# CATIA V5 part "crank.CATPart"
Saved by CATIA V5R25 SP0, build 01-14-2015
Part number: crank
Bounding box of the stored display mesh (mm): x 0 to 2.5, y -5 to 40, z -5 to 5
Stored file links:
  C:\Users\Aidata\Downloads\chapter4\chapter4\crank.CATPart
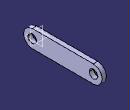
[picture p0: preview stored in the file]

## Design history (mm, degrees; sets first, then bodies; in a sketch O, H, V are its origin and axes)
Body1 (main body)
  Sketch1 on yz-plane, origin (0, 0, 0), H (0, 1, 0), V (0, 0, 1)
    construction line L1 (0, 0) -> (35, 0)
    line L2 (0, 5) -> (35, 5)
    line L3 (35, -5) -> (0, -5)
    arc A1 centre (35, 0) radius 5 from (35, 5) to (35, -5) cw
    arc A2 centre (0, 0) radius 5 from (0, -5) to (0, 5) cw
    circle A3 centre (35, 0) radius 2.5
    circle A4 centre (0, 0) radius 2.5
    distance L1 L2 = 5
    length L2 = 35
    radius A3 = 2.5
    radius A4 = 2.5
    horizontal: L1 H
    tangency: A1 L2, A2 L2, A1 L3, A2 L3
  Pad1: profile Sketch1, direction (1, 0, 0), length 2.5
